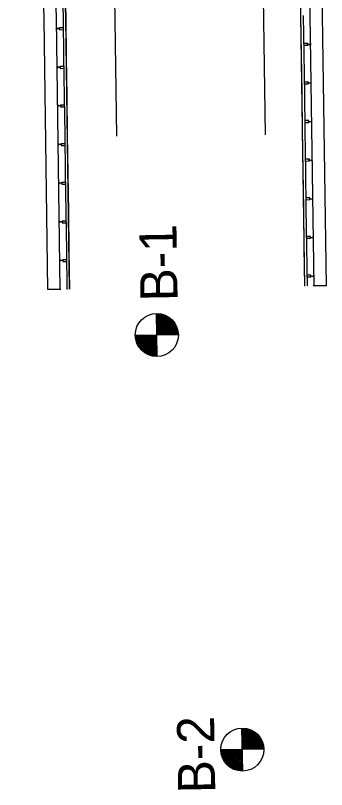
# Model space of a CAD drawing. Extents: x 1676488 to 1677396, y 227642 to 230038.
# Drawn here: x 1677345.7 to 1677395.9, y 229111.5 to 229236.7 of the extents above; entities that cross this region are included whole.
import ezdxf

# ---------------------------------------------------------------- set-up
doc = ezdxf.new("R2010")
doc.units = 0
for name, color, linetype in [('R_BoreHole', 7, 'Continuous'), ('R_Draft', 7, 'Continuous'), ('R_No Plot', 7, 'Continuous'), ('R_Proposed Road_Lane', 7, 'Continuous'), ('R_Proposed Road_Shoulder', 7, 'Continuous'), ('R_Steel', 7, 'Continuous')]:
    doc.layers.add(name, color=color, linetype=linetype)

msp = doc.modelspace()

# ---------------------------------------------------------------- linework, layer by layer
at = {"layer": 'R_BoreHole'}
for p, q in [((1677368.59, 229181.49), (1677368.48, 229188.45)), ((1677368.73, 229184.97), (1677368.68, 229188.45)), ((1677368.93, 229184.98), (1677368.88, 229188.43)), ((1677369.13, 229184.98), (1677369.08, 229188.41)), ((1677369.33, 229184.98), (1677369.28, 229188.37)), ((1677369.53, 229184.99), (1677369.48, 229188.32)), ((1677369.73, 229184.99), (1677369.68, 229188.25)), ((1677369.93, 229184.99), (1677369.88, 229188.18)), ((1677370.13, 229185), (1677370.08, 229188.08)), ((1677370.33, 229185), (1677370.28, 229187.98)), ((1677370.53, 229185), (1677370.49, 229187.85)), ((1677370.73, 229185.01), (1677370.69, 229187.7)), ((1677370.93, 229185.01), (1677370.89, 229187.53)), ((1677371.13, 229185.01), (1677371.09, 229187.32)), ((1677371.33, 229185.02), (1677371.3, 229187.08)), ((1677371.53, 229185.02), (1677371.5, 229186.78)), ((1677371.73, 229185.02), (1677371.71, 229186.39)), ((1677372.01, 229185.03), (1677365.05, 229184.91)), ((1677365.15, 229184.18), (1677365.13, 229184.91)), ((1677365.36, 229183.55), (1677365.33, 229184.92)), ((1677365.56, 229183.16), (1677365.53, 229184.92)), ((1677365.77, 229182.86), (1677365.73, 229184.92)), ((1677365.97, 229182.62), (1677365.93, 229184.93)), ((1677366.18, 229182.41), (1677366.13, 229184.93)), ((1677366.38, 229182.24), (1677366.33, 229184.93)), ((1677366.58, 229182.09), (1677366.53, 229184.94)), ((1677366.78, 229181.96), (1677366.73, 229184.94)), ((1677366.98, 229181.85), (1677366.93, 229184.94)), ((1677367.19, 229181.76), (1677367.13, 229184.95)), ((1677367.39, 229181.68), (1677367.33, 229184.95)), ((1677367.59, 229181.62), (1677367.53, 229184.95)), ((1677367.79, 229181.57), (1677367.73, 229184.96)), ((1677367.99, 229181.53), (1677367.93, 229184.96)), ((1677368.19, 229181.51), (1677368.13, 229184.96)), ((1677368.39, 229181.49), (1677368.33, 229184.97)), ((1677371.93, 229185.03), (1677371.92, 229185.76)), ((1677382.4, 229114.44), (1677382.28, 229121.4)), ((1677382.54, 229117.93), (1677382.48, 229121.4)), ((1677382.74, 229117.93), (1677382.68, 229121.38)), ((1677382.94, 229117.93), (1677382.88, 229121.36)), ((1677383.14, 229117.94), (1677383.08, 229121.32)), ((1677383.34, 229117.94), (1677383.28, 229121.27)), ((1677383.54, 229117.94), (1677383.48, 229121.21)), ((1677383.74, 229117.95), (1677383.69, 229121.13)), ((1677383.94, 229117.95), (1677383.89, 229121.04)), ((1677384.14, 229117.95), (1677384.09, 229120.93)), ((1677384.34, 229117.96), (1677384.29, 229120.8)), ((1677384.54, 229117.96), (1677384.49, 229120.65)), ((1677384.74, 229117.96), (1677384.7, 229120.48)), ((1677384.94, 229117.97), (1677384.9, 229120.28)), ((1677385.14, 229117.97), (1677385.1, 229120.03)), ((1677385.34, 229117.97), (1677385.31, 229119.73)), ((1677385.54, 229117.98), (1677385.52, 229119.34)), ((1677385.74, 229117.98), (1677385.73, 229118.71)), ((1677385.82, 229117.98), (1677378.86, 229117.86)), ((1677378.95, 229117.13), (1677378.94, 229117.87)), ((1677379.16, 229116.5), (1677379.14, 229117.87)), ((1677379.37, 229116.11), (1677379.34, 229117.87)), ((1677379.57, 229115.81), (1677379.54, 229117.88)), ((1677379.78, 229115.57), (1677379.74, 229117.88)), ((1677379.98, 229115.36), (1677379.94, 229117.88)), ((1677380.18, 229115.19), (1677380.14, 229117.89)), ((1677380.39, 229115.04), (1677380.34, 229117.89)), ((1677380.59, 229114.92), (1677380.54, 229117.89)), ((1677380.79, 229114.81), (1677380.74, 229117.9)), ((1677380.99, 229114.71), (1677380.94, 229117.9)), ((1677381.19, 229114.64), (1677381.14, 229117.9)), ((1677381.39, 229114.57), (1677381.34, 229117.91)), ((1677381.6, 229114.52), (1677381.54, 229117.91)), ((1677381.8, 229114.49), (1677381.74, 229117.91)), ((1677382, 229114.46), (1677381.94, 229117.92)), ((1677382.2, 229114.45), (1677382.14, 229117.92))]:
    msp.add_line(p, q, dxfattribs=at)
for centre in [(1677368.53, 229184.97), (1677382.34, 229117.92)]:
    msp.add_circle(centre, 3.48, dxfattribs=at)
at = {"layer": 'R_No Plot'}
for points in [[(1677392.43, 229192.9), (1677391.81, 229236.65), (1677391.35, 229411.66)], [(1677354.43, 229192.37), (1677353.82, 229236.11), (1677349.36, 229411.07)]]:
    msp.add_lwpolyline(points, dxfattribs=at)
at = {"layer": 'R_Proposed Road_Lane'}
for p, q in [((1677362.08, 229217.16), (1677355.47, 229687.53)), ((1677386.08, 229217.34), (1677379.47, 229687.87))]:
    msp.add_line(p, q, dxfattribs=at)
at = {"layer": 'R_Proposed Road_Shoulder'}
for p, q in [((1677353.06, 229192.35), (1677350.93, 229192.32)), ((1677395.93, 229192.95), (1677393.8, 229192.92))]:
    msp.add_line(p, q, dxfattribs=at)
for points in [[(1677350.93, 229192.32), (1677350.32, 229236.07), (1677345.86, 229411.02), (1677345.72, 229421.02), (1677350.75, 229454.09)], [(1677395.93, 229192.95), (1677395.31, 229236.7), (1677394.85, 229411.71), (1677394.71, 229421.71), (1677388.75, 229454.63)]]:
    msp.add_lwpolyline(points, dxfattribs=at)
at = {"layer": 'R_Steel'}
for p, q in [((1677352.34, 229234.69), (1677352.35, 229234.69)), ((1677352.34, 229234.36), (1677352.36, 229234.36)), ((1677352.82, 229234.54), (1677352.36, 229234.53)), ((1677352.82, 229234.52), (1677352.36, 229234.51)), ((1677352.82, 229234.7), (1677352.84, 229234.7)), ((1677352.83, 229234.36), (1677352.84, 229234.36)), ((1677352.84, 229234.7), (1677353.42, 229234.7)), ((1677352.84, 229234.36), (1677353.43, 229234.37)), ((1677392.88, 229232.15), (1677392.29, 229232.15)), ((1677392.88, 229231.82), (1677392.3, 229231.81)), ((1677392.89, 229232.15), (1677392.88, 229232.15)), ((1677392.9, 229231.82), (1677392.88, 229231.82)), ((1677392.9, 229232), (1677393.36, 229232)), ((1677392.9, 229231.98), (1677393.36, 229231.99)), ((1677393.38, 229232.16), (1677393.36, 229232.16)), ((1677393.38, 229231.83), (1677393.37, 229231.83)), ((1677352.43, 229228.44), (1677352.44, 229228.44)), ((1677352.43, 229228.11), (1677352.45, 229228.11)), ((1677352.9, 229228.29), (1677352.45, 229228.28)), ((1677352.9, 229228.27), (1677352.45, 229228.26)), ((1677352.91, 229228.45), (1677352.93, 229228.45)), ((1677352.92, 229228.11), (1677352.93, 229228.11)), ((1677352.93, 229228.45), (1677353.51, 229228.45)), ((1677352.93, 229228.11), (1677353.51, 229228.12)), ((1677392.97, 229225.9), (1677392.38, 229225.9)), ((1677392.97, 229225.57), (1677392.39, 229225.56)), ((1677392.98, 229225.91), (1677392.97, 229225.9)), ((1677392.98, 229225.57), (1677392.97, 229225.57)), ((1677392.99, 229225.75), (1677393.44, 229225.75)), ((1677392.99, 229225.73), (1677393.44, 229225.74)), ((1677393.47, 229225.91), (1677393.45, 229225.91)), ((1677393.47, 229225.58), (1677393.45, 229225.58)), ((1677352.51, 229222.19), (1677352.53, 229222.19)), ((1677352.52, 229221.86), (1677352.53, 229221.86)), ((1677352.99, 229222.04), (1677352.54, 229222.03)), ((1677352.99, 229222.02), (1677352.54, 229222.02)), ((1677353, 229222.2), (1677353.01, 229222.2)), ((1677353, 229221.86), (1677353.02, 229221.86)), ((1677353.01, 229222.2), (1677353.6, 229222.2)), ((1677353.02, 229221.86), (1677353.6, 229221.87)), ((1677393.05, 229219.66), (1677392.47, 229219.65)), ((1677393.06, 229219.32), (1677392.47, 229219.31)), ((1677393.07, 229219.66), (1677393.05, 229219.66)), ((1677393.07, 229219.32), (1677393.06, 229219.32)), ((1677393.08, 229219.5), (1677393.53, 229219.5)), ((1677393.08, 229219.48), (1677393.53, 229219.49)), ((1677393.55, 229219.66), (1677393.54, 229219.66)), ((1677393.56, 229219.33), (1677393.54, 229219.33)), ((1677352.6, 229215.94), (1677352.62, 229215.94)), ((1677352.61, 229215.61), (1677352.62, 229215.61)), ((1677353.08, 229215.79), (1677352.63, 229215.78)), ((1677353.08, 229215.77), (1677352.63, 229215.77)), ((1677353.09, 229215.95), (1677353.1, 229215.95)), ((1677353.09, 229215.61), (1677353.11, 229215.61)), ((1677353.1, 229215.95), (1677353.68, 229215.96)), ((1677353.11, 229215.61), (1677353.69, 229215.62)), ((1677393.14, 229213.41), (1677392.56, 229213.4)), ((1677393.15, 229213.07), (1677392.56, 229213.06)), ((1677393.16, 229213.41), (1677393.14, 229213.41)), ((1677393.16, 229213.07), (1677393.15, 229213.07)), ((1677393.17, 229213.25), (1677393.62, 229213.25)), ((1677393.17, 229213.23), (1677393.62, 229213.24)), ((1677393.64, 229213.41), (1677393.62, 229213.41)), ((1677393.65, 229213.08), (1677393.63, 229213.08)), ((1677352.69, 229209.69), (1677352.71, 229209.69)), ((1677352.69, 229209.36), (1677352.71, 229209.36)), ((1677353.17, 229209.54), (1677352.72, 229209.53)), ((1677353.17, 229209.52), (1677352.72, 229209.52)), ((1677353.17, 229209.7), (1677353.19, 229209.7)), ((1677353.18, 229209.36), (1677353.19, 229209.36)), ((1677353.19, 229209.7), (1677353.77, 229209.71)), ((1677353.19, 229209.36), (1677353.78, 229209.37)), ((1677393.23, 229207.16), (1677392.65, 229207.15)), ((1677393.23, 229206.82), (1677392.65, 229206.81)), ((1677393.24, 229207.16), (1677393.23, 229207.16)), ((1677393.25, 229206.82), (1677393.23, 229206.82)), ((1677393.25, 229207), (1677393.71, 229207)), ((1677393.25, 229206.98), (1677393.71, 229206.99)), ((1677393.73, 229207.16), (1677393.71, 229207.16)), ((1677393.73, 229206.83), (1677393.72, 229206.83)), ((1677352.78, 229203.44), (1677352.79, 229203.44)), ((1677352.78, 229203.11), (1677352.8, 229203.11)), ((1677353.26, 229203.29), (1677352.8, 229203.28)), ((1677353.26, 229203.27), (1677352.8, 229203.27)), ((1677353.26, 229203.45), (1677353.28, 229203.45)), ((1677353.27, 229203.11), (1677353.28, 229203.11)), ((1677353.28, 229203.45), (1677353.86, 229203.46)), ((1677353.28, 229203.11), (1677353.86, 229203.12)), ((1677393.32, 229200.91), (1677392.73, 229200.9)), ((1677393.32, 229200.57), (1677392.74, 229200.56)), ((1677393.33, 229200.91), (1677393.32, 229200.91)), ((1677393.34, 229200.57), (1677393.32, 229200.57)), ((1677393.34, 229200.75), (1677393.79, 229200.75)), ((1677393.34, 229200.73), (1677393.79, 229200.74)), ((1677393.82, 229200.91), (1677393.8, 229200.91)), ((1677393.82, 229200.58), (1677393.81, 229200.58)), ((1677352.86, 229197.19), (1677352.88, 229197.19)), ((1677352.87, 229196.86), (1677352.89, 229196.86)), ((1677353.34, 229197.04), (1677352.89, 229197.03)), ((1677353.34, 229197.02), (1677352.89, 229197.02)), ((1677353.35, 229197.2), (1677353.36, 229197.2)), ((1677353.35, 229196.86), (1677353.37, 229196.86)), ((1677353.36, 229197.2), (1677353.95, 229197.21)), ((1677353.37, 229196.86), (1677353.95, 229196.87)), ((1677393.4, 229194.66), (1677392.82, 229194.65)), ((1677393.41, 229194.32), (1677392.83, 229194.32)), ((1677393.42, 229194.66), (1677393.4, 229194.66)), ((1677393.42, 229194.32), (1677393.41, 229194.32)), ((1677393.43, 229194.5), (1677393.88, 229194.51)), ((1677393.43, 229194.48), (1677393.88, 229194.49)), ((1677393.9, 229194.66), (1677393.89, 229194.66)), ((1677393.91, 229194.33), (1677393.89, 229194.33))]:
    msp.add_line(p, q, dxfattribs=at)
for points in [[(1677393.93, 229192.92), (1677393.31, 229236.67), (1677392.85, 229411.68)], [(1677352.93, 229192.35), (1677352.32, 229236.09), (1677347.86, 229411.05)], [(1677353.24, 229242.37), (1677353.4, 229236.12)], [(1677353.66, 229242.38), (1677353.82, 229236.13)], [(1677391.9, 229230.4), (1677391.81, 229236.65)], [(1677392.32, 229230.41), (1677392.23, 229236.65)], [(1677353.4, 229236.11), (1677353.49, 229229.86)], [(1677353.82, 229236.12), (1677353.91, 229229.87)], [(1677352.34, 229234.69), (1677352.34, 229234.36)], [(1677352.35, 229234.69), (1677352.36, 229234.54)], [(1677352.36, 229234.51), (1677352.36, 229234.36)], [(1677352.82, 229234.7), (1677352.82, 229234.54)], [(1677352.83, 229234.51), (1677352.83, 229234.36)], [(1677352.84, 229234.7), (1677352.84, 229234.36)], [(1677353.42, 229234.7), (1677353.43, 229234.37)], [(1677392.3, 229231.81), (1677392.29, 229232.15)], [(1677392.88, 229231.82), (1677392.88, 229232.15)], [(1677392.89, 229232), (1677392.89, 229232.15)], [(1677392.9, 229231.82), (1677392.89, 229231.97)], [(1677393.36, 229232.01), (1677393.36, 229232.16)], [(1677393.37, 229231.83), (1677393.36, 229231.98)], [(1677393.38, 229231.83), (1677393.38, 229232.16)], [(1677391.99, 229224.15), (1677391.9, 229230.4)], [(1677392.41, 229224.16), (1677392.32, 229230.41)], [(1677353.49, 229229.86), (1677353.58, 229223.61)], [(1677353.91, 229229.87), (1677353.99, 229223.62)], [(1677352.43, 229228.44), (1677352.43, 229228.11)], [(1677352.44, 229228.44), (1677352.44, 229228.29)], [(1677352.44, 229228.26), (1677352.45, 229228.11)], [(1677352.91, 229228.45), (1677352.91, 229228.3)], [(1677352.91, 229228.26), (1677352.92, 229228.11)], [(1677352.93, 229228.45), (1677352.93, 229228.11)], [(1677353.51, 229228.45), (1677353.51, 229228.12)], [(1677392.39, 229225.56), (1677392.38, 229225.9)], [(1677392.97, 229225.57), (1677392.97, 229225.9)], [(1677392.98, 229225.76), (1677392.98, 229225.91)], [(1677392.98, 229225.57), (1677392.98, 229225.72)], [(1677393.45, 229225.76), (1677393.45, 229225.91)], [(1677393.45, 229225.58), (1677393.45, 229225.73)], [(1677393.47, 229225.58), (1677393.47, 229225.91)], [(1677392.08, 229217.9), (1677391.99, 229224.15)], [(1677392.49, 229217.91), (1677392.41, 229224.16)], [(1677353.58, 229223.61), (1677353.66, 229217.36)], [(1677353.99, 229223.62), (1677354.08, 229217.37)], [(1677352.51, 229222.19), (1677352.52, 229221.86)], [(1677352.53, 229222.19), (1677352.53, 229222.04)], [(1677352.53, 229222.01), (1677352.53, 229221.86)], [(1677353, 229222.2), (1677353, 229222.05)], [(1677353, 229222.01), (1677353, 229221.86)], [(1677353.01, 229222.2), (1677353.02, 229221.86)], [(1677353.6, 229222.2), (1677353.6, 229221.87)], [(1677392.47, 229219.31), (1677392.47, 229219.65)], [(1677393.06, 229219.32), (1677393.05, 229219.66)], [(1677393.07, 229219.51), (1677393.07, 229219.66)], [(1677393.07, 229219.32), (1677393.07, 229219.47)], [(1677393.54, 229219.51), (1677393.54, 229219.66)], [(1677393.54, 229219.33), (1677393.54, 229219.48)], [(1677393.56, 229219.33), (1677393.55, 229219.66)], [(1677392.17, 229211.65), (1677392.08, 229217.9)], [(1677392.58, 229211.66), (1677392.49, 229217.91)], [(1677353.66, 229217.36), (1677353.75, 229211.11)], [(1677354.08, 229217.37), (1677354.17, 229211.12)], [(1677352.6, 229215.94), (1677352.61, 229215.61)], [(1677352.62, 229215.94), (1677352.62, 229215.79)], [(1677352.62, 229215.76), (1677352.62, 229215.61)], [(1677353.09, 229215.95), (1677353.09, 229215.8)], [(1677353.09, 229215.76), (1677353.09, 229215.61)], [(1677353.1, 229215.95), (1677353.11, 229215.61)], [(1677353.68, 229215.96), (1677353.69, 229215.62)], [(1677392.56, 229213.06), (1677392.56, 229213.4)], [(1677393.15, 229213.07), (1677393.14, 229213.41)], [(1677393.16, 229213.26), (1677393.16, 229213.41)], [(1677393.16, 229213.07), (1677393.16, 229213.22)], [(1677393.63, 229213.26), (1677393.62, 229213.41)], [(1677393.63, 229213.08), (1677393.63, 229213.23)], [(1677393.65, 229213.08), (1677393.64, 229213.41)], [(1677392.25, 229205.4), (1677392.17, 229211.65)], [(1677392.67, 229205.41), (1677392.58, 229211.66)], [(1677353.75, 229211.11), (1677353.84, 229204.86)], [(1677354.17, 229211.12), (1677354.26, 229204.87)], [(1677352.69, 229209.69), (1677352.69, 229209.36)], [(1677352.71, 229209.69), (1677352.71, 229209.54)], [(1677352.71, 229209.51), (1677352.71, 229209.36)], [(1677353.17, 229209.7), (1677353.18, 229209.55)], [(1677353.18, 229209.51), (1677353.18, 229209.36)], [(1677353.19, 229209.7), (1677353.19, 229209.36)], [(1677353.77, 229209.71), (1677353.78, 229209.37)], [(1677392.65, 229206.81), (1677392.65, 229207.15)], [(1677393.23, 229206.82), (1677393.23, 229207.16)], [(1677393.25, 229207.01), (1677393.24, 229207.16)], [(1677393.25, 229206.82), (1677393.25, 229206.97)], [(1677393.71, 229207.01), (1677393.71, 229207.16)], [(1677393.72, 229206.83), (1677393.72, 229206.98)], [(1677393.73, 229206.83), (1677393.73, 229207.16)], [(1677392.34, 229199.15), (1677392.25, 229205.4)], [(1677392.76, 229199.16), (1677392.67, 229205.41)], [(1677353.84, 229204.86), (1677353.93, 229198.61)], [(1677354.26, 229204.87), (1677354.34, 229198.62)], [(1677352.78, 229203.44), (1677352.78, 229203.11)], [(1677352.79, 229203.44), (1677352.8, 229203.29)], [(1677352.8, 229203.26), (1677352.8, 229203.11)], [(1677353.26, 229203.45), (1677353.26, 229203.3)], [(1677353.26, 229203.26), (1677353.27, 229203.11)], [(1677353.28, 229203.45), (1677353.28, 229203.11)], [(1677353.86, 229203.46), (1677353.86, 229203.12)], [(1677392.74, 229200.56), (1677392.73, 229200.9)], [(1677393.32, 229200.57), (1677393.32, 229200.91)], [(1677393.33, 229200.76), (1677393.33, 229200.91)], [(1677393.34, 229200.57), (1677393.33, 229200.72)], [(1677393.8, 229200.76), (1677393.8, 229200.91)], [(1677393.81, 229200.58), (1677393.8, 229200.73)], [(1677393.82, 229200.58), (1677393.82, 229200.91)], [(1677353.93, 229198.61), (1677354.02, 229192.36)], [(1677354.34, 229198.62), (1677354.43, 229192.37)], [(1677392.43, 229192.9), (1677392.34, 229199.15)], [(1677392.85, 229192.91), (1677392.76, 229199.16)], [(1677352.86, 229197.19), (1677352.87, 229196.86)], [(1677352.88, 229197.19), (1677352.88, 229197.04)], [(1677352.88, 229197.01), (1677352.89, 229196.86)], [(1677353.35, 229197.2), (1677353.35, 229197.05)], [(1677353.35, 229197.01), (1677353.35, 229196.86)], [(1677353.36, 229197.2), (1677353.37, 229196.86)], [(1677353.95, 229197.21), (1677353.95, 229196.87)], [(1677392.83, 229194.32), (1677392.82, 229194.65)], [(1677393.41, 229194.32), (1677393.4, 229194.66)], [(1677393.42, 229194.51), (1677393.42, 229194.66)], [(1677393.42, 229194.32), (1677393.42, 229194.47)], [(1677393.89, 229194.51), (1677393.89, 229194.66)], [(1677393.89, 229194.33), (1677393.89, 229194.48)], [(1677393.91, 229194.33), (1677393.9, 229194.66)]]:
    msp.add_lwpolyline(points, dxfattribs=at)

# ---------------------------------------------------------------- texts
at = {"layer": 'R_Draft'}
for s, p in [('B-1', (1677371.9, 229190.46)), ('B-2', (1677377.98, 229110.89))]:
    msp.add_text(s, height=6, rotation=90.9497, dxfattribs=at).set_placement(p)

doc.saveas('drawing.dxf')
